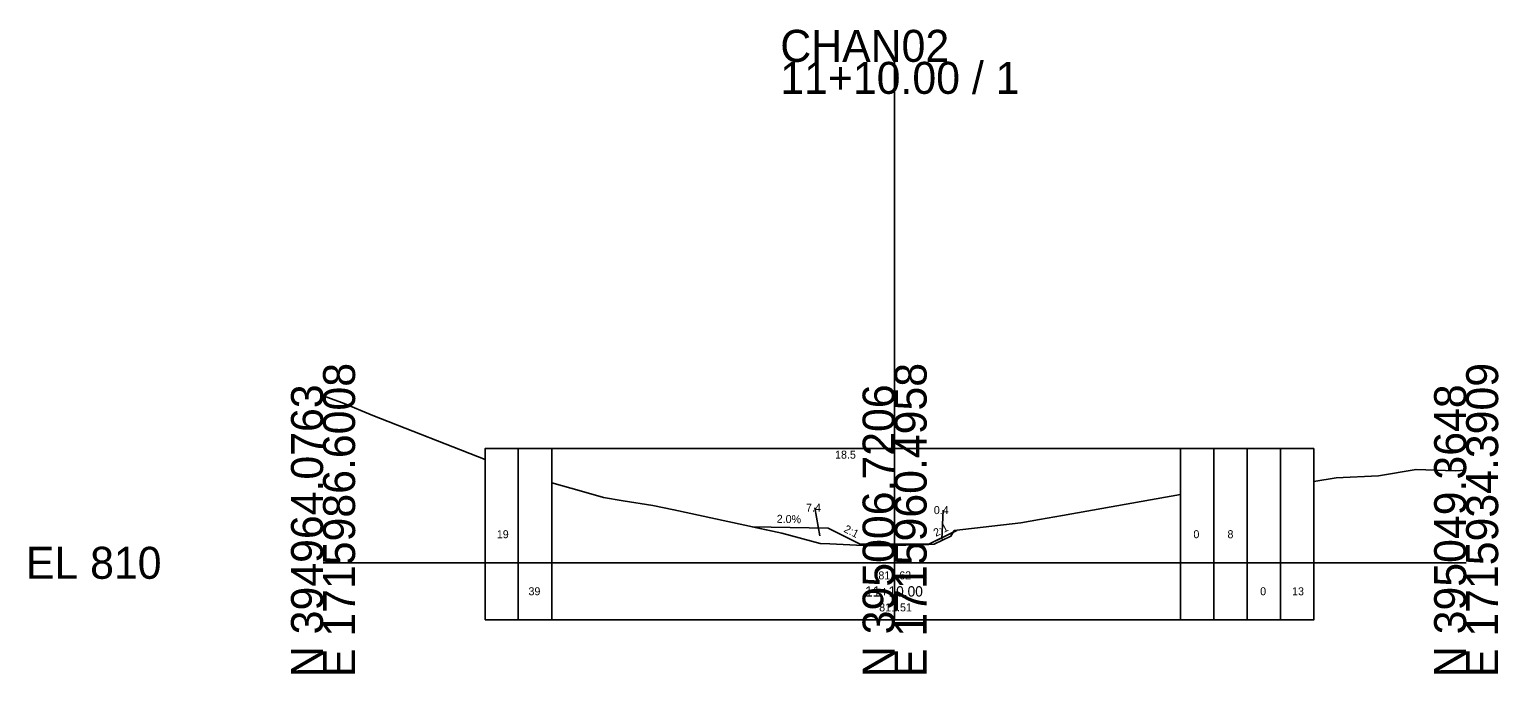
# Model space of a CAD drawing. Extents: x -26 to 103, y -10 to 16052.
# Drawn here: x -25.7 to 102.8, y 11990.3 to 12046.7 of the extents above; entities that cross this region are included whole.
import ezdxf

# ---------------------------------------------------------------- set-up
doc = ezdxf.new("R2010")
doc.units = 0
for name, color, linetype in [('GK_Cells', 7, 'Continuous'), ('SH_Text', 7, 'Continuous'), ('XS_P_Annotation', 7, 'Continuous'), ('XS_P_Boundary', 7, 'Continuous'), ('XS_P_Earthwork_Shapes', 7, 'Continuous'), ('XS_P_Finished_Grade', 7, 'Continuous'), ('XS_X_Ground_Line', 7, 'Continuous')]:
    doc.layers.add(name, color=color, linetype=linetype)

msp = doc.modelspace()

# ---------------------------------------------------------------- linework, layer by layer
at = {"layer": 'GK_Cells'}
for p, q in [((50, 12000), (50, 12043.82)), ((0, 12000), (50, 12000)), ((50, 12000), (100, 12000))]:
    msp.add_line(p, q, dxfattribs=at)
at = {"layer": 'XS_P_Boundary'}
for p, q in [((17.08, 11995.01), (17.08, 12009.99)), ((20, 11995.01), (20, 12009.99)), ((50, 11995.01), (50, 12009.99)), ((75, 11995.01), (75, 12009.99)), ((77.92, 11995.01), (77.92, 12009.99)), ((80.83, 11995.01), (80.83, 12009.99)), ((83.75, 11995.01), (83.75, 12009.99)), ((15.63, 12002.5), (15.63, 12002.5)), ((76.46, 12002.5), (76.46, 12002.5)), ((79.38, 12002.5), (79.38, 12002.5)), ((18.54, 11997.51), (18.54, 11997.51)), ((82.29, 11997.51), (82.29, 11997.51)), ((85.21, 11997.51), (85.21, 11997.51))]:
    msp.add_line(p, q, dxfattribs=at)
msp.add_lwpolyline([(14.17, 11995.01), (14.17, 12009.99), (86.67, 12009.99), (86.67, 11995.01)], close=True, dxfattribs=at)
at = {"layer": 'XS_P_Earthwork_Shapes'}
for p, q in [((43.47, 12002.36), (43.03, 12004.82)), ((54.14, 12002.08), (54.25, 12004.61)), ((44.19, 12003.02), (37.54, 12003.16)), ((37.54, 12003.16), (40.14, 12002.59)), ((47, 12001.62), (44.19, 12003.02)), ((55.13, 12002.69), (53, 12001.62)), ((53, 12001.62), (47, 12001.62)), ((53, 12001.61), (53.47, 12001.63))]:
    msp.add_line(p, q, dxfattribs=at)
for points in [[(37.54, 12003.16), (44.19, 12003.02), (47, 12001.62), (53, 12001.62), (55.45, 12002.84)], [(40.14, 12002.59), (43.5, 12001.69), (44.32, 12001.65), (47.82, 12001.48), (49.66, 12001.5), (50, 12001.51), (53, 12001.61)], [(53.47, 12001.63), (54.93, 12002.34), (55.13, 12002.69)], [(53, 12001.61), (53, 12001.62)], [(53, 12001.62), (53, 12001.61)]]:
    msp.add_lwpolyline(points, dxfattribs=at)
at = {"layer": 'XS_P_Finished_Grade'}
for p, q in [((44.19, 12003.02), (37.54, 12003.16)), ((44.19, 12003.02), (47, 12001.62)), ((55.45, 12002.84), (53, 12001.62)), ((47, 12001.62), (53, 12001.62))]:
    msp.add_line(p, q, dxfattribs=at)
at = {"layer": 'XS_X_Ground_Line'}
for points in [[(0, 12014.61), (1.71, 12013.99), (4.35, 12012.88), (14.17, 12009.03)], [(86.67, 12007.12), (88.64, 12007.43), (92.32, 12007.61), (95.62, 12008.17), (99.03, 12008.05), (100, 12008.11)], [(20, 12007), (22.61, 12006.26), (24.54, 12005.71), (26.25, 12005.43), (28.84, 12005), (30.69, 12004.64), (40.14, 12002.59), (43.5, 12001.69), (44.32, 12001.65), (47.82, 12001.48), (49.66, 12001.5), (50, 12001.51), (53.47, 12001.63), (54.93, 12002.34), (55.21, 12002.82), (61.05, 12003.51), (62.68, 12003.8), (64.68, 12004.15), (75, 12005.97)]]:
    msp.add_lwpolyline(points, dxfattribs=at)

# ---------------------------------------------------------------- texts
at = {"layer": 'GK_Cells'}
for s, p in [('CHAN02', (40, 12043.82)), ('11+10.00 / 1', (40, 12041.02)), ('EL 810', (-26, 11998.6))]:
    msp.add_text(s, height=2.8, dxfattribs=at).set_placement(p)
for s, p in [('E 1715986.6008', (2.8, 11990)), ('E 1715960.4958', (52.8, 11990)), ('E 1715934.3909', (102.8, 11990)), ('N 394964.0763', (0, 11990)), ('N 395006.7206', (50, 11990)), ('N 395049.3648', (100, 11990))]:
    msp.add_text(s, height=2.8, rotation=90, dxfattribs=at).set_placement(p)
at = {"layer": 'SH_Text'}
for s, p in [('19', (15.2, 12002.15)), ('0', (76.14, 12002.15)), ('8', (79.12, 12002.15)), ('39', (17.97, 11997.16)), ('0', (81.98, 11997.16)), ('13', (84.77, 11997.16))]:
    msp.add_text(s, height=0.7, dxfattribs=at).set_placement(p)
at = {"layer": 'XS_P_Annotation'}
for s, rotation, p in [('2.0%', 358.8542, (39.68, 12003.5)), ('2:1', 333.4349, (45.49, 12002.73)), ('2:1', 26.5651, (53.61, 12002.26))]:
    msp.add_text(s, height=0.7, rotation=rotation, dxfattribs=at).set_placement(p)
for s, height, p in [('811.62', 0.7, (48.58, 11998.55)), ('11+10.00', 0.9, (47.42, 11997.05)), ('811.51', 0.7, (48.65, 11995.75))]:
    msp.add_text(s, height=height, dxfattribs=at).set_placement(p)
at = {"layer": 'XS_P_Earthwork_Shapes'}
for s, p in [('18.5', (44.79, 12009.11)), ('7.4', (42.25, 12004.47)), ('0.4', (53.43, 12004.26))]:
    msp.add_text(s, height=0.7, dxfattribs=at).set_placement(p)

doc.saveas('drawing.dxf')
